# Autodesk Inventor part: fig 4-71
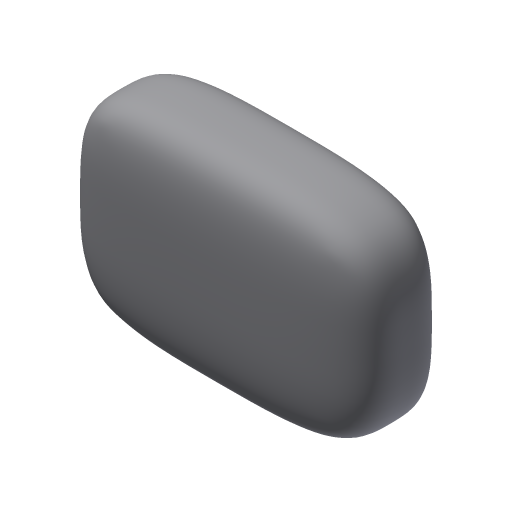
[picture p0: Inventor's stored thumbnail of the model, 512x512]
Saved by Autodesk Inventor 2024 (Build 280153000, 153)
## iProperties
Created: 2012-07
Part Number: fig 4-71
Material: Generic
Document SubType Name: Modeling
Designer: CADCIM
Density: 1 g/cm^3
Appearance: Default
Author: CADCIM
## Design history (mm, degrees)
feature "Form1"
body "Solid1"
body "Solid2"
